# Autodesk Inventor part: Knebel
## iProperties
Created: 2009-10
Part Number: Knebel
Cost Center: 0 kg
Material: 3.3206 AlMgSi0,5
Description: Startmodell Bauteil
Document SubType Name: Modeling
Designer: BoseDa
Authority: 0 mm^3
Manufacturer: Standard
Standards Organization: Custom
Density: 2.66 g/cm^3
Company: Grenzebach BSH
Author: BoseDa
FileName: Norm
SaveDate: 2008-11-23
SaveTime: 16:30
TotalMass: 0 kg
TotalVolume: 0 mm^3
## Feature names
1. Umdrehung1 [Revolution]
